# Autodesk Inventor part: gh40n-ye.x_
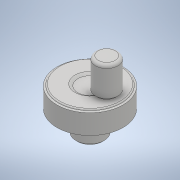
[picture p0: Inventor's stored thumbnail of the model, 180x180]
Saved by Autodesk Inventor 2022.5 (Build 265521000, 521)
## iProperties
Part Number: gh40n-ye.x_
Material: 一般
Document SubType Name: Modeling
Designer: ImaoCorp
Density: 1 g/cm^3
Appearance: 既定
Sending System: SOLIDWORKS 2017-2017317
MC: AMD64
MC_MODEL: Intel64 Family 6 Model 60 Stepping 3, GenuineIntel
OS: Windows_NT
FRU: Parasolid Version 29.0, build 201,  4-17-2017
FORMAT: text
GUISE: transmit
KEY: gh40n-ye
FILE: gh40n-ye.x_t
DATE: Mon Jul 01 17:31:56 2019
Author: ImaoCorp
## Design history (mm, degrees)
feature "Base1"
node "ソリッド1"
